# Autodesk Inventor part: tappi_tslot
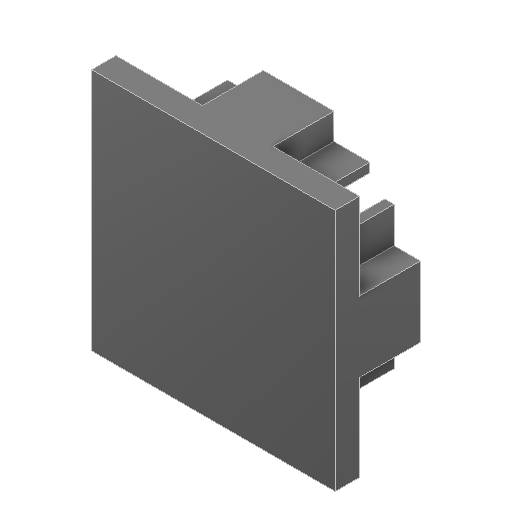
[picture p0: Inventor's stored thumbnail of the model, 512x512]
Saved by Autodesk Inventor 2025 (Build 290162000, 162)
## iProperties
Created: 2025-05
Part Number: tappi_tslot
Material: Plastica ABS
Document SubType Name: Modeling
Designer: R5800u
Density: 1.06 g/cm^3
Appearance: Liscia - Nero
Author: R5800u
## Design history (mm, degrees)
sketch "Schizzo1"
  geometry: L1 (-10, -10)-(10, -10); L2 (10, -10)-(10, 10); L3 (10, 10)-(-10, 10); L4 (-10, 10)-(-10, -10); L5 (-10, -10)-(10, 10); L6 (10, -10)-(-10, 10); 1 further point
  constraints: 12 end point, 2 midpoint, 2 parallel, 1 horizontal, 1 perpendicular
  dimensions: "d0" = 20 distance of L3.end L2.end; "d1" = 20 distance of L2.end L1.end
extrude "Estrusione1" new body sketch "Schizzo1" distance "d2" = 2; taper "d3" = 0 deg
sketch "Schizzo3"
  geometry: L1 (-10, -10)-(-10, 10) reference; L2 (-10, -2.898)-(-7.84, -2.898); L3 (-7.84, -2.898)-(-7.84, -5.843); L4 (-7.84, -5.843)-(-7.082, -5.843); L5 (-7.082, -5.843)-(-4.099, -2.898); L6 (-4.099, -2.898)-(-4.099, 0); L7 (-4.099, 0)-(-10, 0); L8 (-10, -2.898)-(-10, 0); L9 (-10, 2.898)-(-7.84, 2.898); L10 (-7.84, 2.898)-(-7.84, 5.843); L11 (-7.84, 5.843)-(-7.082, 5.843); L12 (-7.082, 5.843)-(-4.099, 2.898); L13 (-4.099, 2.898)-(-4.099, 0); L14 (-10, 2.898)-(-10, 0); L15 (-2.898, 10)-(-2.898, 7.84); L16 (-2.898, 7.84)-(-5.843, 7.84); L17 (-5.843, 7.84)-(-5.843, 7.082); L18 (-5.843, 7.082)-(-2.898, 4.099); L19 (-2.898, 4.099)-(0, 4.099); L20 (0, 4.099)-(0, 10); L21 (-2.898, 10)-(0, 10); L22 (2.898, 10)-(2.898, 7.84); L23 (2.898, 7.84)-(5.843, 7.84); L24 (5.843, 7.84)-(5.843, 7.082); L25 (5.843, 7.082)-(2.898, 4.099); L26 (2.898, 4.099)-(0, 4.099); L27 (2.898, 10)-(0, 10); L28 (10, 2.898)-(7.84, 2.898); L29 (7.84, 2.898)-(7.84, 5.843); L30 (7.84, 5.843)-(7.082, 5.843); L31 (7.082, 5.843)-(4.099, 2.898); L32 (4.099, 2.898)-(4.099, 0); L33 (4.099, 0)-(10, 0); L34 (10, 2.898)-(10, 0); L35 (10, -2.898)-(7.84, -2.898); L36 (7.84, -2.898)-(7.84, -5.843); L37 (7.84, -5.843)-(7.082, -5.843); L38 (7.082, -5.843)-(4.099, -2.898); L39 (4.099, -2.898)-(4.099, 0); L40 (10, -2.898)-(10, 0); L41 (2.898, -10)-(2.898, -7.84); L42 (2.898, -7.84)-(5.843, -7.84); L43 (5.843, -7.84)-(5.843, -7.082); L44 (5.843, -7.082)-(2.898, -4.099); L45 (2.898, -4.099)-(0, -4.099); L46 (0, -4.099)-(0, -10); L47 (2.898, -10)-(0, -10); L48 (-2.898, -10)-(-2.898, -7.84); L49 (-2.898, -7.84)-(-5.843, -7.84); L50 (-5.843, -7.84)-(-5.843, -7.082); L51 (-5.843, -7.082)-(-2.898, -4.099); L52 (-2.898, -4.099)-(0, -4.099); L53 (-2.898, -10)-(0, -10); C1 r 2 at (0, 0); 2 further points
  constraints: 104 end point, 9 point on line, 5 symmetric about line, 2 perpendicular, 1 centre point, 1 coincident, 1 collinear, 1 horizontal, 1 midpoint, 1 parallel, 101 other
  dimensions: "d5" = 4 diameter of C1; "d10" = 360 deg dimension on point (0, 0) L2.start (derived)
extrude "Estrusione2" join sketch "Schizzo3" distance "d6" = 5; taper "d7" = 0 deg
node "Solido1"
node "Schizzo - Serie circolare1" dims "d10" = 360 deg (derived)
